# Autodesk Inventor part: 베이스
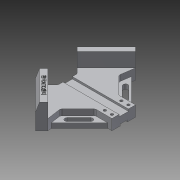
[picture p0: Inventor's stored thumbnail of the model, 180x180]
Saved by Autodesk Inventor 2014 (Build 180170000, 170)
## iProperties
Created: 2020-05
Part Number: 베이스
Material: Aluminum 6061
Document SubType Name: Modeling
Designer: kh
Density: 2.71 g/cm^3
Appearance: Aluminum - Flat
Mass: 573.739 g
Surface Area: 407.173 cm^2
Volume: 211.712 cm^3
Author: kh
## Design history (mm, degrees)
sketch "Sketch1"
  geometry: L1 (0, 0)-(0, 298.702); L2 (-20, 0)-(20, 0); L3 (20, 0)-(84.853, 64.853); L4 (84.853, 64.853)-(35.355, 114.35); L5 (35.355, 114.35)-(16.005, 95); L6 (16.005, 95)-(-16.005, 95); L7 (-16.005, 95)-(-35.355, 114.35); L8 (-35.355, 114.35)-(-84.853, 64.853); L9 (-84.853, 64.853)-(-20, 0); 1 further point
  constraints: 18 end point, 4 perpendicular, 3 parallel, 2 midpoint, 1 point on line, 1 vertical
  dimensions: "d7" = 40 distance of L2.end L2.start; "d8" = 120 distance between parallel lines of L4 L9; "d10" = 50 distance between parallel lines of L4 L7; "d12" = 120 distance between parallel lines of L3 L8; "d13" = 50 distance from line of L4.end L8; "d14" = 95 distance between parallel lines of L2 L6
extrude "Extrusion1" new body sketch "Sketch1" distance "d15" = 18; taper "d16" = 0 deg
sketch "Sketch2"
  geometry: L1 (16.005, 95)-(-16.005, 95) reference; L2 (-20, 0)-(20, 0) reference; L3 (-8, 95)-(8, 95); L4 (8, 95)-(8, 0); L5 (8, 0)-(-8, 0); L6 (-8, 0)-(-8, 95); L7 (0, 0)-(0, 111.993)
  constraints: 10 end point, 3 parallel, 2 point on line, 1 horizontal, 1 perpendicular, 1 other
  dimensions: "d17" = 16 distance between parallel lines of L4 L6
extrude "Extrusion2" cut sketch "Sketch2" distance "d18" = 3.5; taper "d19" = 0 deg
sketch "Sketch3"
  geometry: L1 (-84.853, 64.853)-(-20, 0) reference; L2 (-35.355, 114.35)-(-84.853, 64.853) reference; L3 (-49.497, 57.782)-(-20, 28.284); L4 (-74.246, 54.246)-(-95.959, 32.534); L5 (-74.246, 54.246)-(-49.497, 57.782); L6 (-49.497, 57.782)-(-76.437, 30.842); L7 (-20, 0)-(-20, 28.284); L8 (-74.246, 54.246)-(-20, 0); 1 further point
  constraints: 12 end point, 2 perpendicular, 1 parallel, 1 point on line, 1 vertical
  dimensions: "d20" = 20 distance from line of L3.start L1; "d21" = 15 distance between parallel lines of L4 L2; "d22" = 30 distance between parallel lines of L6 L2
extrude "Extrusion3" cut sketch "Sketch3" distance "d23" = 10; taper "d24" = 0 deg
sketch "Sketch4"
  geometry: L1 (-20, 28.284)-(-20, 0) reference; L2 (-20, 0)-(-74.246, 54.246) reference; L3 (-68.059, 55.13)-(-20, 7.071); L4 (-20, 28.284)-(-20, 0) reference; L5 (-49.497, 57.782)-(-20, 28.284) reference; L6 (-74.246, 54.246)-(-49.497, 57.782) reference; L7 (-20, 0)-(-74.246, 54.246) reference; L8 (-74.246, 54.246)-(-20, 0); L9 (-20, 0)-(-20, 7.071); L10 (-74.246, 54.246)-(-68.059, 55.13); 1 further point
  constraints: 8 end point, 3 collinear, 2 point on line
  dimensions: "d25" = 5 distance between parallel lines of L3 L2
extrude "Extrusion4" cut sketch "Sketch4" distance "d26" = 10; taper "d27" = 0 deg
sketch "Sketch5"
  geometry: L1 (-68.059, 55.13)-(-20, 7.071) reference; L2 (-20, 28.284)-(-20, 7.071) reference; L3 (-49.497, 57.782)-(-20, 28.284) reference; L4 (-68.059, 55.13)-(-49.497, 57.782) reference; L5 (-49.497, 46.468)-(-29.698, 26.669); L6 (-52.326, 43.64)-(-32.527, 23.841); L7 (-26.87, 29.497)-(-46.669, 49.296); L8 (-35.355, 114.35)-(-84.853, 64.853) reference; A1 r 4 centre (-49.497, 46.468) between (-46.669, 49.296) and (-52.326, 43.64); A2 r 4 centre (-29.698, 26.669) between (-32.527, 23.841) and (-26.87, 29.497); 2 further points
  constraints: 8 end point, 4 point on circle, 4 tangent, 2 centre point, 2 parallel, 1 midpoint
  dimensions: "d28" = 8 distance between parallel lines of L7 L6; "d29" = 38 distance from line of L5.start L8; "d30" = 28 distance of L5.start L5.end; "d31" = 7 distance from line of L5.start L1
extrude "Extrusion5" cut sketch "Sketch5" stored distance "d32" = 10; taper "d33" = 0 deg
sketch "Sketch6"
  geometry: L1 (-84.853, 64.853)-(-74.246, 54.246) reference; L2 (-35.355, 114.35)-(-84.853, 64.853) reference; L3 (-16.005, 95)-(-35.355, 114.35) reference; L4 (-74.246, 54.246)-(-24.749, 103.744); L5 (-74.246, 54.246)-(-84.853, 64.853); L6 (-84.853, 64.853)-(-35.355, 114.35); L7 (-35.355, 114.35)-(-24.749, 103.744); 1 further point
  constraints: 8 end point, 2 collinear, 2 perpendicular, 1 point on line
extrude "Extrusion6" join sketch "Sketch6" distance "d34" = 24; taper "d35" = 0 deg
sketch "Sketch9"
  geometry: L1 (0, 0)-(-15, 0) reference; L2 (0, 42)-(0, 0) reference; L3 (-5, 0)-(0, 15); L4 (-5, 0)-(0.988, 0); L5 (0, 15)-(0, 0); 1 further point
  constraints: 6 end point, 2 perpendicular, 2 point on line
  dimensions: "d36" = 5 distance of L1.start L3.start; "d37" = 15 vertical distance of L3.end L3.start
extrude "Extrusion7" cut sketch "Sketch9" stored distance "d38" = 24; taper "d39" = 0 deg
mirror "Mirror1"
sketch "Sketch10"
  geometry: L1 (-16.005, 95)-(16.005, 95) reference; L2 (20, 0)-(-20, 0) reference; L3 (-6, 95)-(6, 95); L4 (6, 95)-(6, 0); L5 (6, 0)-(-6, 0); L6 (-6, 0)-(-6, 95); L7 (0, 0)-(0, 108.009)
  constraints: 10 end point, 3 parallel, 2 point on line, 1 horizontal, 1 perpendicular, 1 other
  dimensions: "d40" = 12 distance between parallel lines of L4 L6
extrude "Extrusion8" cut sketch "Sketch10" distance "d41" = 3; taper "d42" = 0 deg
sketch "Sketch11"
  geometry: L1 (0, 0)-(0, 51.762); L2 (20, 0)-(6, 0) reference; L3 (-20, 7.071)-(-20, 0) reference; L4 (20, 0)-(20, 7.071) reference; L5 (-74.246, 54.246)-(-84.853, 64.853) reference; L6 (84.853, 64.853)-(74.246, 54.246) reference; 4 further points
  constraints: 2 end point, 2 symmetric about line, 1 vertical
  dimensions: "d43" = 28 distance of point (14, 6) point (-14, 6); "d44" = 6 distance from line of point (14, 6) L2; "d45" = 12 distance of point (14, 18) point (14, 6); "d46" = 28 distance of point (14, 18) point (-14, 18)
hole "Hole1" sketch "Sketch11" at (-14, 6), (-14, 18), (14, 6), (14, 18) diameter "d47" = 4.5; stored, may be unused: countersink angle "d51" = 90 deg, drill point angle "d53" = 118 deg; dims "d48" = 6, "d49" = 8, "d50" = 10, "d52" = 8
sketch "Sketch12"
  geometry: L1 (-31.261, 97.159)-(-67.662, 60.759); L2 (-67.662, 60.759)-(-74.805, 67.902); L3 (-74.805, 67.902)-(-38.404, 104.302); L4 (-38.404, 104.302)-(-31.261, 97.159); L5 (-31.82, 110.815)-(-81.317, 61.317) reference; L6 (-56.605, 86.102)-(-49.461, 78.959); L7 (-71.233, 64.33)-(-34.833, 100.731); L8 (-74.246, 54.246)-(-24.749, 103.744) reference; L9 (-24.749, 103.744)-(-31.82, 110.815) reference; 1 further point
  constraints: 4 end point, 4 midpoint, 1 perpendicular, 2 other
  dimensions: "d54" = 5 distance from line of L7.end L8; "d55" = 35 distance from line of L6.end L9
emboss "Emboss1" sketch "Sketch12" dims "d56" = 0.5, "d57" = 0
fillet "Fillet1" dims "d58" = 5
body "Solid1"
node "Projected Loop1"
node "Projected Loop2"
